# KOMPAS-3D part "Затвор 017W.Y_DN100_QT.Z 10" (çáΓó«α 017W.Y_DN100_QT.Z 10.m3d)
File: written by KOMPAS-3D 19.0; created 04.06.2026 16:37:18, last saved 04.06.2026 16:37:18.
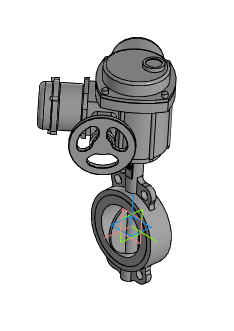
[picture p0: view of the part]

Document properties: Автор: Энергия; Полное имя файла: ..\..\..\3d для проектировщиков\017W разные\x.x Тип 017W.Y(S) Затвор дисковый поворотный межфланцевый\Затвор 017W.Y(S)_DN32-DN450_QT.Z\Затвор 017W.Y_DN100_QT.Z 10.a3d

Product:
- Part/product: Затвор 017W.Y_DN100_QT.Z 10
    Масса: 34.3387

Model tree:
1. Операция без истории:1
